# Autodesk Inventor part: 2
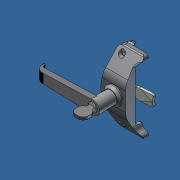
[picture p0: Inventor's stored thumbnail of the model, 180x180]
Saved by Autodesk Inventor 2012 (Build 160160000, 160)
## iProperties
Created: 2014-06
Part Number: 2
Material: Default
Document SubType Name: Modeling
Designer: Admin
Density: 1 g/cm^3
Mass: 101.685 g
Surface Area: 371.616 cm^2
Volume: 101.685 cm^3
Translation Standard: STEP AP214IS
FileName: 21_0949_0_1.stp
PreProcessor: ACIS
PostProcessor: Build: 160, Release: 2012 RTM - Date: Tue 03/01/2011
Sent Units: millimeter
Uncertainty: 0.0
Author: Admin
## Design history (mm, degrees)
feature "Base1"
body "Solid1"
